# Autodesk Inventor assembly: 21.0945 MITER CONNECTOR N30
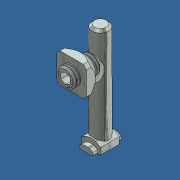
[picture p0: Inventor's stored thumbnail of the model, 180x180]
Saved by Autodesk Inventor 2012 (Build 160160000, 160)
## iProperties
Created: 2012-10
Part Number: 21.0945 MITER CONNECTOR N30
Document SubType Name: Assembly
Designer: Administrator
Author: Administrator
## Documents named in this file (4)
- C:\Andys Backup Data\ANDY'S INVENTOR\INVENTOR LIBRARIES\PARTS LIBRARY\30 SERIES\21.0945 MITER CONNECTOR N30.iam
- C:\Andys Backup Data\ANDY'S INVENTOR\INVENTOR LIBRARIES\PARTS LIBRARY\30 SERIES\SUBCOMPONENTS\21.0945 MITER CONNECTOR N30.ipt
- C:\Andys Backup Data\ANDY'S INVENTOR\INVENTOR LIBRARIES\PARTS LIBRARY\FASTENING ELEMENTS\NUTS\21.1351 M8 SQUARE NUT.ipt
- C:\Andys Backup Data\ANDY'S INVENTOR\INVENTOR LIBRARIES\PARTS LIBRARY\FASTENING ELEMENTS\SET SCREWS\21.1303 M8X14 T-SLOT BAR SET SCREW.ipt
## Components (3 placed, 3 different names)
1. 21.0945 MITER CONNECTOR N30:1 — Angle:1, Angle:2, Mate:2, Flush:1, Mate:3, Mate:4, Flush:2
2. 21.1351 M8 SQUARE NUT:1 — Angle:1, Angle:2, Mate:2, Angle:3, Flush:1, Mate:5
3. 21.1303 M8X14 T-SLOT BAR SET SCREW:1 — Angle:3, Mate:3, Mate:4, Flush:2, Mate:5
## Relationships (9: Mate 4, Angle 3, Flush 2)
- Angle:1: 21.0945 MITER CONNECTOR N30:1 ↔ 21.1351 M8 SQUARE NUT:1
- Angle:2: 21.0945 MITER CONNECTOR N30:1 ↔ 21.1351 M8 SQUARE NUT:1
- Mate:2: 21.0945 MITER CONNECTOR N30:1 ↔ 21.1351 M8 SQUARE NUT:1
- Angle:3: 21.1351 M8 SQUARE NUT:1 ↔ 21.1303 M8X14 T-SLOT BAR SET SCREW:1
- Flush:1: 21.0945 MITER CONNECTOR N30:1 ↔ 21.1351 M8 SQUARE NUT:1
- Mate:3: 21.0945 MITER CONNECTOR N30:1 ↔ 21.1303 M8X14 T-SLOT BAR SET SCREW:1
- Mate:4: 21.0945 MITER CONNECTOR N30:1 ↔ 21.1303 M8X14 T-SLOT BAR SET SCREW:1
- Flush:2: 21.0945 MITER CONNECTOR N30:1 ↔ 21.1303 M8X14 T-SLOT BAR SET SCREW:1
- Mate:5: 21.1351 M8 SQUARE NUT:1 ↔ 21.1303 M8X14 T-SLOT BAR SET SCREW:1
